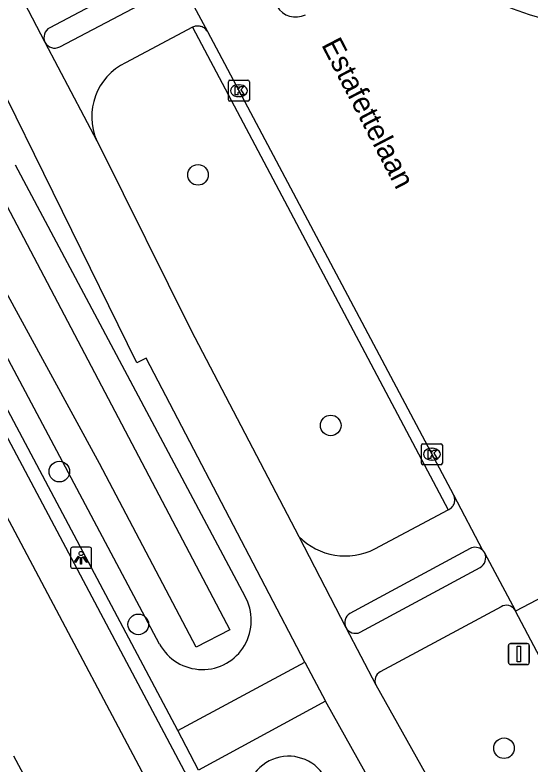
# Model space of a CAD drawing. Extents: x 158838 to 160074, y 386376 to 387776.
# Drawn here: x 159217.42 to 159241.91, y 387112.04 to 387147.63 of the extents above; entities that cross this region are included whole.
import ezdxf

# ---------------------------------------------------------------- set-up
doc = ezdxf.new("R2010")
doc.units = 0
for name, color, linetype in [('IMGEO_Berm_groen', 7, 'Continuous'), ('IMGEO_Berm_open', 7, 'Continuous'), ('IMGEO_Boom', 7, 'Continuous'), ('IMGEO_Fietspad_gesloten', 7, 'Continuous'), ('IMGEO_Fietspad_open', 7, 'Continuous'), ('IMGEO_Kolk', 7, 'Continuous'), ('IMGEO_Lichtpunt', 7, 'Continuous'), ('IMGEO_Openbare_ruimte_label', 7, 'Continuous'), ('IMGEO_Rijbaan_lokaal_gesloten', 7, 'Continuous'), ('IMGEO_Rijbaan_lokaal_open', 7, 'Continuous'), ('IMGEO_Verkeersbordpaal', 7, 'Continuous'), ('IMGEO_Voetpad_open', 7, 'Continuous'), ('IMGEO_Waterloop', 7, 'Continuous')]:
    doc.layers.add(name, color=color, linetype=linetype)

msp = doc.modelspace()

# ---------------------------------------------------------------- linework, layer by layer
at = {"layer": 'IMGEO_Berm_groen'}
for points in [[(159217.424, 387140.529), (159228.33, 387120.048)], [(159224.283, 387117.778), (159213.314, 387138.385)]]:
    msp.add_lwpolyline(points, dxfattribs=at)
for centre, radius, start, end in [((159226.317, 387118.894), 2.32, 208.7533, 29.8236), ((159230.405, 387110.451), 2.01, 31.3221, 193.0582)]:
    msp.add_arc(centre, radius, start, end, dxfattribs=at)
at = {"layer": 'IMGEO_Berm_open'}
msp.add_lwpolyline([(159225.85, 387147.049), (159237.983, 387124.154)], dxfattribs=at)
at = {"layer": 'IMGEO_Boom'}
for centre in [(159226.107, 387140.046), (159232.403, 387128.156), (159219.528, 387125.966), (159223.274, 387118.716), (159240.627, 387112.84)]:
    msp.add_circle(centre, 0.489, dxfattribs=at)
at = {"layer": 'IMGEO_Fietspad_gesloten'}
for points in [[(159217.45, 387149.028), (159218.846, 387146.337)], [(159218.846, 387146.337), (159221.304, 387141.66)], [(159231.17, 387116.927), (159223.64, 387131.346), (159223.201, 387131.121), (159216.131, 387145.48)], [(159221.304, 387141.66), (159221.481, 387141.323), (159225.771, 387132.689), (159230.892, 387122.887)], [(159230.892, 387122.887), (159233.118, 387118.571)], [(159233.118, 387118.571), (159234.539, 387115.845)], [(159231.17, 387116.927), (159232.161, 387115.069)], [(159234.539, 387115.845), (159274.567, 387044.384)], [(159272.288, 387043.244), (159232.161, 387115.069)]]:
    msp.add_lwpolyline(points, dxfattribs=at)
at = {"layer": 'IMGEO_Fietspad_open'}
for points in [[(159219.548, 387146.121), (159224.876, 387148.928)], [(159225.85, 387147.049), (159222.672, 387145.363)], [(159226.555, 387146.843), (159226.529, 387146.883), (159226.499, 387146.921), (159226.467, 387146.956), (159226.431, 387146.988), (159226.392, 387147.016), (159226.351, 387147.041), (159226.308, 387147.062), (159226.264, 387147.079), (159226.218, 387147.093), (159226.171, 387147.102), (159226.123, 387147.107), (159226.075, 387147.107), (159226.027, 387147.103), (159225.98, 387147.095), (159225.934, 387147.083), (159225.889, 387147.067), (159225.85, 387147.049)], [(159237.983, 387124.154), (159238.024, 387124.174), (159238.062, 387124.197), (159238.099, 387124.224), (159238.133, 387124.253), (159238.164, 387124.286), (159238.192, 387124.321), (159238.217, 387124.359), (159238.238, 387124.399), (159238.256, 387124.44), (159238.27, 387124.483), (159238.28, 387124.527), (159238.286, 387124.572), (159238.288, 387124.617), (159238.286, 387124.662), (159238.28, 387124.707), (159238.27, 387124.751), (159238.256, 387124.794), (159238.238, 387124.836), (159238.227, 387124.858)], [(159234.497, 387122.302), (159237.983, 387124.154)], [(159239.016, 387122.309), (159233.313, 387119.226)]]:
    msp.add_lwpolyline(points, dxfattribs=at)
for centre, radius, start, end in [((159219.307, 387146.585), 0.523, 208.309, 297.4855), ((159223.895, 387142.807), 2.833, 115.5666, 203.8819), ((159233.09, 387125.035), 3.073, 224.3312, 297.2342), ((159239.262, 387121.87), 0.503, 46.3789, 119.2046), ((159233.573, 387118.792), 0.506, 120.916, 205.9264)]:
    msp.add_arc(centre, radius, start, end, dxfattribs=at)
at = {"layer": 'IMGEO_Kolk'}
for p, q in [((159227.622, 387144.538), (159228.474, 387144.538)), ((159227.547, 387143.612), (159227.547, 387144.464)), ((159228.035, 387144.318), (159228.06, 387144.318)), ((159228.548, 387144.464), (159228.548, 387143.612)), ((159228.474, 387143.538), (159227.622, 387143.538)), ((159228.058, 387143.758), (159228.033, 387143.758)), ((159236.705, 387126.364), (159236.705, 387127.216)), ((159236.78, 387127.29), (159237.632, 387127.29)), ((159237.706, 387127.216), (159237.706, 387126.364)), ((159237.193, 387127.07), (159237.218, 387127.07)), ((159237.216, 387126.51), (159237.191, 387126.51)), ((159237.632, 387126.29), (159236.78, 387126.29))]:
    msp.add_line(p, q, dxfattribs=at)
for points in [[(159227.622, 387144.538), (159228.474, 387144.538)], [(159227.547, 387143.612), (159227.547, 387144.464)], [(159227.868, 387144.238), (159227.991, 387144.238), (159227.991, 387144.087), (159228.121, 387144.238), (159228.285, 387144.238), (159228.139, 387144.087), (159228.292, 387143.838), (159228.14, 387143.838), (159228.055, 387144.002), (159227.991, 387143.935), (159227.991, 387143.838), (159227.868, 387143.838), (159227.868, 387144.238)], [(159228.548, 387144.464), (159228.548, 387143.612)], [(159228.474, 387143.538), (159227.622, 387143.538)], [(159236.705, 387126.364), (159236.705, 387127.216)], [(159236.78, 387127.29), (159237.632, 387127.29)], [(159237.706, 387127.216), (159237.706, 387126.364)], [(159237.026, 387126.99), (159237.149, 387126.99), (159237.149, 387126.839), (159237.279, 387126.99), (159237.443, 387126.99), (159237.297, 387126.839), (159237.45, 387126.59), (159237.298, 387126.59), (159237.213, 387126.754), (159237.149, 387126.687), (159237.149, 387126.59), (159237.026, 387126.59), (159237.026, 387126.99)], [(159237.632, 387126.29), (159236.78, 387126.29)]]:
    msp.add_lwpolyline(points, dxfattribs=at)
for centre, start, end in [((159227.624, 387144.462), 91.552, 178.448), ((159227.624, 387144.462), 91.552, 178.448), ((159228.472, 387144.462), 1.552, 88.448), ((159228.472, 387144.462), 1.552, 88.448), ((159227.624, 387143.614), 181.552, 268.448), ((159227.624, 387143.614), 181.552, 268.448), ((159228.472, 387143.614), 271.552, 358.448), ((159228.472, 387143.614), 271.552, 358.448), ((159236.782, 387127.214), 91.552, 178.448), ((159236.782, 387127.214), 91.552, 178.448), ((159237.63, 387127.214), 1.552, 88.448), ((159237.63, 387127.214), 1.552, 88.448), ((159236.782, 387126.366), 181.552, 268.448), ((159236.782, 387126.366), 181.552, 268.448), ((159237.63, 387126.366), 271.552, 358.448), ((159237.63, 387126.366), 271.552, 358.448)]:
    msp.add_arc(centre, 0.0765, start, end, dxfattribs=at)
for centre, major_axis, ratio, start_param, end_param in [((159228.034, 387144.038), (-0.387, 0.002), 0.722429, 4.712389, 7.853982), ((159228.059, 387144.038), (-0.39, 0.002), 0.717154, 1.570796, 4.712389), ((159237.192, 387126.79), (-0.387, 0.002), 0.722429, 4.712389, 7.853982), ((159237.217, 387126.79), (-0.39, 0.002), 0.717154, 1.570796, 4.712389)]:
    msp.add_ellipse(centre, major_axis=major_axis, ratio=ratio, start_param=start_param, end_param=end_param, dxfattribs=at)
at = {"layer": 'IMGEO_Lichtpunt'}
for p, q in [((159220.062, 387122.281), (159220.062, 387121.474)), ((159220.062, 387122.281), (159220.062, 387121.474)), ((159220.964, 387122.376), (159220.156, 387122.376)), ((159220.964, 387122.376), (159220.156, 387122.376)), ((159221.058, 387121.474), (159221.058, 387122.281)), ((159221.058, 387121.474), (159221.058, 387122.281)), ((159220.156, 387121.38), (159220.964, 387121.38)), ((159220.156, 387121.38), (159220.964, 387121.38))]:
    msp.add_line(p, q, dxfattribs=at)
for points in [[(159220.436, 387121.945), (159220.475, 387121.917), (159220.287, 387121.655), (159220.249, 387121.682), (159220.436, 387121.945)], [(159220.538, 387121.897), (159220.585, 387121.897), (159220.585, 387121.575), (159220.538, 387121.575), (159220.538, 387121.897)], [(159220.648, 387121.917), (159220.686, 387121.944), (159220.873, 387121.682), (159220.834, 387121.654), (159220.648, 387121.917)]]:
    msp.add_lwpolyline(points, dxfattribs=at)
msp.add_circle((159220.561, 387122.079), 0.0994, dxfattribs=at)
for centre, start, end in [((159220.156, 387122.281), 90, 180), ((159220.156, 387122.281), 90, 180), ((159220.964, 387122.281), 0, 90), ((159220.964, 387122.281), 0, 90), ((159220.156, 387121.474), 180, 270), ((159220.156, 387121.474), 180, 270), ((159220.964, 387121.474), 270, 0), ((159220.964, 387121.474), 270, 360)]:
    msp.add_arc(centre, 0.0946, start, end, dxfattribs=at)
at = {"layer": 'IMGEO_Rijbaan_lokaal_gesloten'}
for points in [[(159225.074, 387149.62), (159226.555, 387146.843)], [(159226.555, 387146.843), (159238.227, 387124.858)], [(159238.227, 387124.858), (159239.609, 387122.234)], [(159239.609, 387122.234), (159239.707, 387122.106)], [(159239.707, 387122.106), (159241.149, 387119.388)], [(159245.482, 387121.606), (159241.175, 387119.339)], [(159241.175, 387119.339), (159241.149, 387119.388)], [(159279.646, 387046.923), (159274.342, 387056.94), (159265.209, 387074.119), (159255.82, 387091.76), (159244.354, 387113.334), (159241.175, 387119.339)]]:
    msp.add_lwpolyline(points, dxfattribs=at)
for centre, radius, start, end in [((159245.158, 387158.06), 10.928, 219.2597, 267.2702), ((159230.74, 387148.544), 1.011, 209.5038, 297.2465)]:
    msp.add_arc(centre, radius, start, end, dxfattribs=at)
at = {"layer": 'IMGEO_Rijbaan_lokaal_open'}
for points in [[(159185.962, 387182.529), (159186.994, 387180.354), (159195.093, 387165.124), (159206.383, 387143.913), (159215.465, 387126.768), (159216.713, 387124.427), (159225.399, 387108.034), (159237.811, 387084.633), (159248.115, 387065.172), (159257.979, 387046.591), (159267.363, 387028.878), (159268.082, 387027.672)], [(159219.95, 387107.637), (159219.855, 387107.834), (159217.374, 387112.457)]]:
    msp.add_lwpolyline(points, dxfattribs=at)
at = {"layer": 'IMGEO_Verkeersbordpaal'}
for p, q in [((159240.837, 387116.908), (159240.837, 387117.708)), ((159240.837, 387117.708), (159240.837, 387116.908)), ((159240.937, 387117.808), (159241.727, 387117.808)), ((159241.727, 387117.808), (159240.937, 387117.808)), ((159241.827, 387117.708), (159241.827, 387116.908)), ((159241.827, 387116.908), (159241.827, 387117.708)), ((159241.727, 387116.808), (159240.937, 387116.808)), ((159240.937, 387116.808), (159241.727, 387116.808))]:
    msp.add_line(p, q, dxfattribs=at)
msp.add_lwpolyline([(159241.257, 387117.683), (159241.407, 387117.683), (159241.407, 387116.933), (159241.257, 387116.933), (159241.257, 387117.683)], dxfattribs=at)
for centre, start, end in [((159240.937, 387117.708), 90, 180), ((159240.937, 387117.708), 90, 180), ((159241.727, 387117.708), 0, 90), ((159241.727, 387117.708), 360, 90), ((159240.937, 387116.908), 180, 270), ((159240.937, 387116.908), 180, 270), ((159241.727, 387116.908), 270, 0), ((159241.727, 387116.908), 270, 0)]:
    msp.add_arc(centre, 0.1, start, end, dxfattribs=at)
at = {"layer": 'IMGEO_Voetpad_open'}
for points in [[(159188.607, 387181.119), (159217.085, 387127.542), (159268.384, 387030.839), (159268.404, 387030.804), (159268.439, 387030.73), (159268.468, 387030.653), (159268.49, 387030.574), (159268.504, 387030.493), (159268.512, 387030.411), (159268.512, 387030.329), (159268.504, 387030.247), (159268.49, 387030.166), (159268.468, 387030.087), (159268.089, 387028.603), (159268.053, 387028.439), (159268.033, 387028.272), (159268.027, 387028.103), (159268.036, 387027.936), (159268.061, 387027.769), (159268.082, 387027.672)], [(159224.376, 387149.83), (159219.072, 387147.028)], [(159225.151, 387113.68), (159209.987, 387142.226)], [(159233.801, 387118.339), (159239.49, 387121.414)], [(159240.486, 387119.556), (159234.758, 387116.463)], [(159225.151, 387113.68), (159231.17, 387116.927)], [(159232.161, 387115.069), (159226.137, 387111.804)], [(159226.137, 387111.804), (159225.151, 387113.68)]]:
    msp.add_lwpolyline(points, dxfattribs=at)
for centre, radius, start, end in [((159219.333, 387146.56), 0.536, 119.1746, 204.6035), ((159239.221, 387121.879), 0.537, 300.1189, 25.0599), ((159240.732, 387119.136), 0.487, 31.1658, 120.396), ((159233.583, 387118.819), 0.527, 208.0423, 294.4347), ((159234.984, 387116.035), 0.484, 117.8486, 203.1259)]:
    msp.add_arc(centre, radius, start, end, dxfattribs=at)
at = {"layer": 'IMGEO_Waterloop'}
msp.add_lwpolyline([(159216.221, 387140.115), (159227.617, 387118.452), (159226.015, 387117.63), (159221.436, 387126.357), (159214.393, 387139.242)], dxfattribs=at)

# ---------------------------------------------------------------- texts
at = {"layer": 'IMGEO_Openbare_ruimte_label'}
msp.add_text('Estafettelaan', height=1, rotation=297.4622, dxfattribs=at).set_placement((159231.941, 387146.219))

doc.saveas('drawing.dxf')
